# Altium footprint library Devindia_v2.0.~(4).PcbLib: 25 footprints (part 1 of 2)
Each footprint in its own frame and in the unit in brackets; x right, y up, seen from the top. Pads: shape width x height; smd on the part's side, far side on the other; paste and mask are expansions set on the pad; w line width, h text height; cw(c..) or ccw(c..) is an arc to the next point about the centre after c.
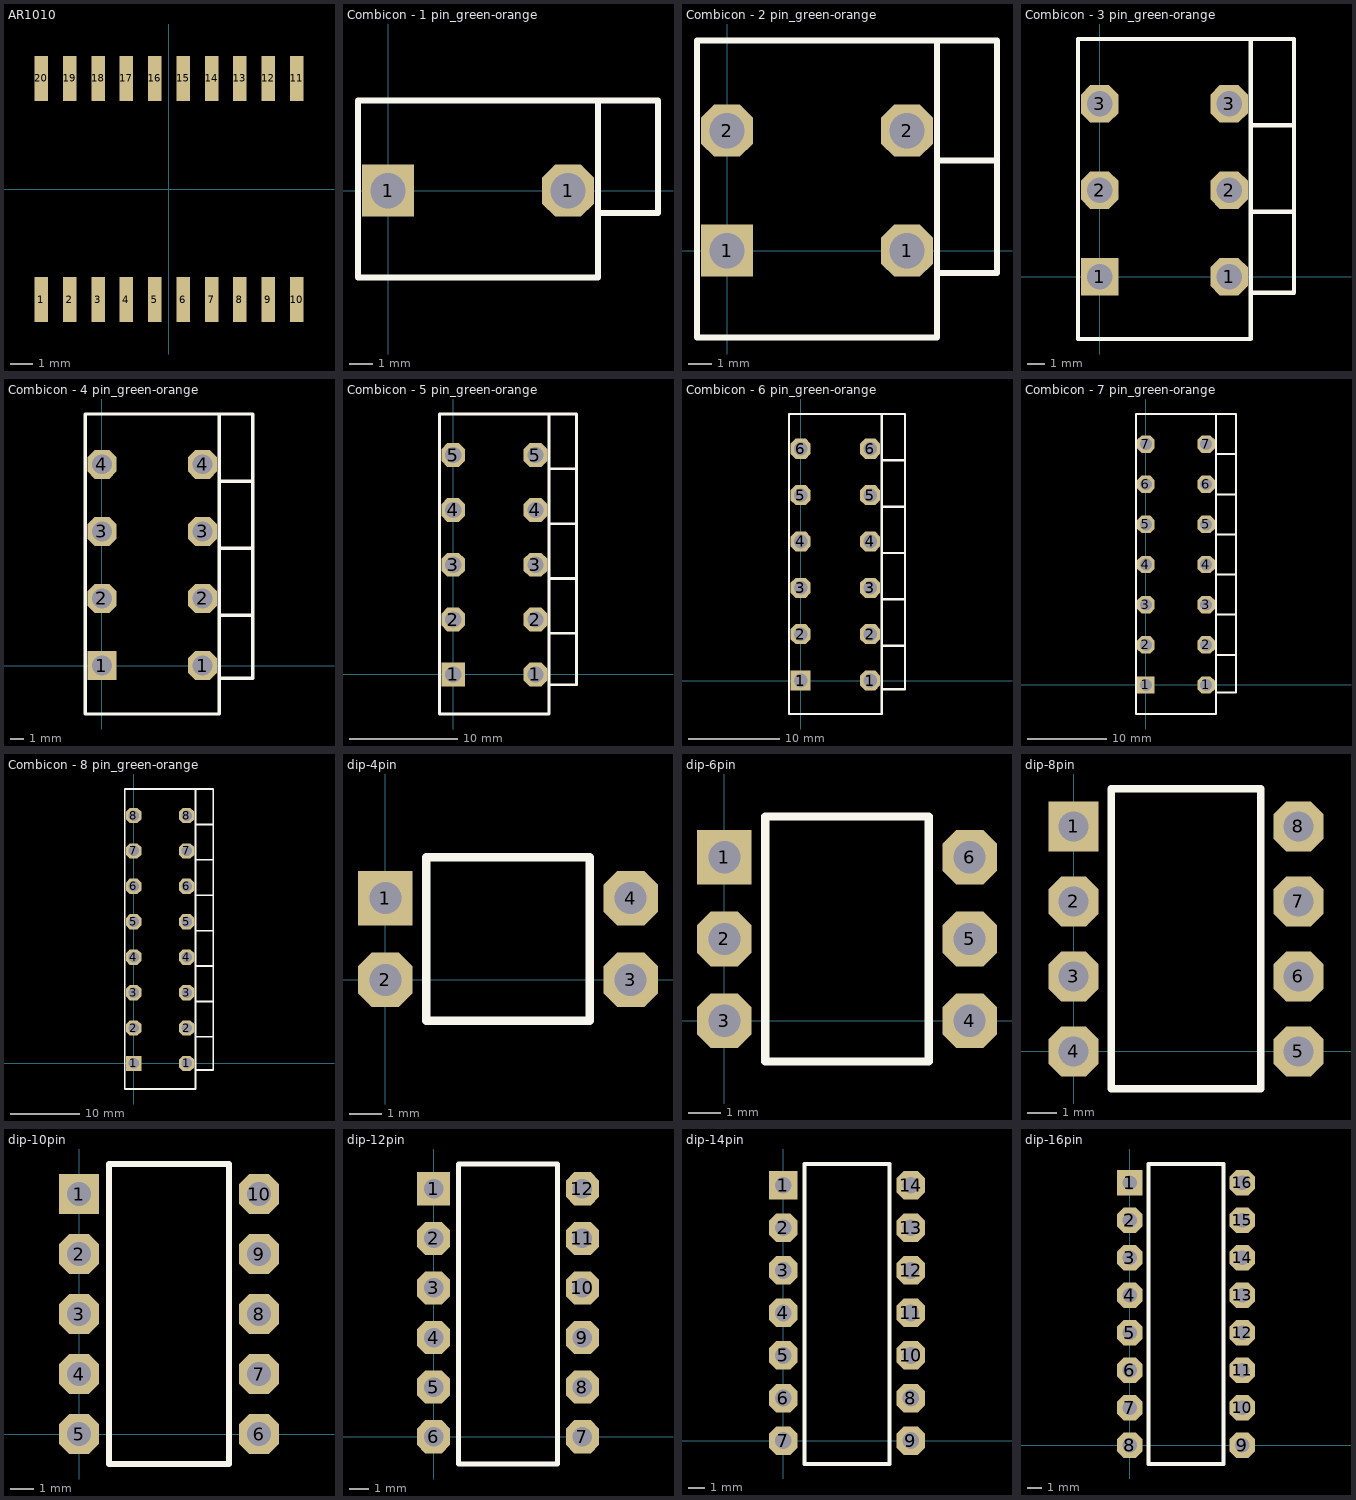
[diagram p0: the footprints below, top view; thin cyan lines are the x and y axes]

## AR1010 [mm]
pads (20):
  rect 0.6x2 smd: 1(-5.715,-4.95) 2(-4.445,-4.95) 3(-3.175,-4.95) 4(-1.905,-4.95) 5(-0.635,-4.95) 6(0.635,-4.95) 7(1.905,-4.95) 8(3.175,-4.95) 9(4.445,-4.95) 10(5.715,-4.95) 11(5.715,4.95) 12(4.445,4.95) 13(3.175,4.95) 14(1.905,4.95) 15(0.635,4.95) 16(-0.635,4.95) 17(-1.905,4.95) 18(-3.175,4.95) 19(-4.445,4.95) 20(-5.715,4.95)
Bottom Overlay:
  circle w0.254: c-5.695,-3.115 r0.284
  lines w0.254: -6.4,-3.75 -6.4,3.75 6.4,3.75 6.4,-3.75 -6.4,-3.75
3D body: height 2.15, standoff 2.05, extent -5.969,-2.54 -5.46,-2.034
3D body: height 0.32, standoff 0, extent -5.969,-5.588 -5.461,-4.318
3D body: height 1, standoff 0.16, extent -5.969,-4.445 -5.461,-4.191
3D body: height 0.32, standoff 0, extent -5.969,-4.51 -5.461,-4.191
3D body: height 1.16, standoff 0.84, extent -5.969,-4.445 -5.461,-4.126
3D body: height 1.16, standoff 0.84, extent -5.969,-4.318 -5.461,-3.175
3D body: height 0.32, standoff 0, extent -4.699,-5.588 -4.191,-4.318
3D body: height 1, standoff 0.16, extent -4.699,-4.445 -4.191,-4.191
3D body: height 0.32, standoff 0, extent -4.699,-4.51 -4.191,-4.191
3D body: height 1.16, standoff 0.84, extent -4.699,-4.445 -4.191,-4.126
3D body: height 1.16, standoff 0.84, extent -4.699,-4.318 -4.191,-3.175
3D body: height 0.32, standoff 0, extent -3.429,-5.588 -2.921,-4.318
3D body: height 1, standoff 0.16, extent -3.429,-4.445 -2.921,-4.191
3D body: height 0.32, standoff 0, extent -3.429,-4.51 -2.921,-4.191
3D body: height 1.16, standoff 0.84, extent -3.429,-4.445 -2.921,-4.126
3D body: height 1.16, standoff 0.84, extent -3.429,-4.318 -2.921,-3.175
3D body: height 0.32, standoff 0, extent -2.159,-5.588 -1.651,-4.318
3D body: height 1, standoff 0.16, extent -2.159,-4.445 -1.651,-4.191
3D body: height 0.32, standoff 0, extent -2.159,-4.51 -1.651,-4.191
3D body: height 1.16, standoff 0.84, extent -2.159,-4.445 -1.651,-4.126
3D body: height 1.16, standoff 0.84, extent -2.159,-4.318 -1.651,-3.175
3D body: height 0.32, standoff 0, extent -0.889,-5.588 -0.381,-4.318
3D body: height 1, standoff 0.16, extent -0.889,-4.445 -0.381,-4.191
3D body: height 0.32, standoff 0, extent -0.889,-4.51 -0.381,-4.191
3D body: height 1.16, standoff 0.84, extent -0.889,-4.445 -0.381,-4.126
3D body: height 1.16, standoff 0.84, extent -0.889,-4.318 -0.381,-3.175
3D body: height 0.32, standoff 0, extent 0.381,-5.588 0.889,-4.318
3D body: height 1, standoff 0.16, extent 0.381,-4.445 0.889,-4.191
3D body: height 0.32, standoff 0, extent 0.381,-4.51 0.889,-4.191
3D body: height 1.16, standoff 0.84, extent 0.381,-4.445 0.889,-4.126
3D body: height 1.16, standoff 0.84, extent 0.381,-4.318 0.889,-3.175
3D body: height 0.32, standoff 0, extent 1.651,-5.588 2.159,-4.318
3D body: height 1, standoff 0.16, extent 1.651,-4.445 2.159,-4.191
3D body: height 0.32, standoff 0, extent 1.651,-4.51 2.159,-4.191
3D body: height 1.16, standoff 0.84, extent 1.651,-4.445 2.159,-4.126
3D body: height 1.16, standoff 0.84, extent 1.651,-4.318 2.159,-3.175
3D body: height 0.32, standoff 0, extent 2.921,-5.588 3.429,-4.318
3D body: height 1, standoff 0.16, extent 2.921,-4.445 3.429,-4.191
3D body: height 0.32, standoff 0, extent 2.921,-4.51 3.429,-4.191
3D body: height 1.16, standoff 0.84, extent 2.921,-4.445 3.429,-4.126
3D body: height 1.16, standoff 0.84, extent 2.921,-4.318 3.429,-3.175
3D body: height 0.32, standoff 0, extent 4.191,-5.588 4.699,-4.318
3D body: height 1, standoff 0.16, extent 4.191,-4.445 4.699,-4.191
3D body: height 0.32, standoff 0, extent 4.191,-4.51 4.699,-4.191
3D body: height 1.16, standoff 0.84, extent 4.191,-4.445 4.699,-4.126
3D body: height 1.16, standoff 0.84, extent 4.191,-4.318 4.699,-3.175
3D body: height 0.32, standoff 0, extent 5.461,-5.588 5.969,-4.318
3D body: height 1, standoff 0.16, extent 5.461,-4.445 5.969,-4.191
3D body: height 0.32, standoff 0, extent 5.461,-4.51 5.969,-4.191
3D body: height 1.16, standoff 0.84, extent 5.461,-4.445 5.969,-4.126
3D body: height 1.16, standoff 0.84, extent 5.461,-4.318 5.969,-3.175
3D body: height 0.32, standoff 0, extent 5.461,4.318 5.969,5.588
3D body: height 1, standoff 0.16, extent 5.461,4.191 5.969,4.445
3D body: height 0.32, standoff 0, extent 5.461,4.191 5.969,4.51
3D body: height 1.16, standoff 0.84, extent 5.461,4.126 5.969,4.445
3D body: height 1.16, standoff 0.84, extent 5.461,3.175 5.969,4.318
3D body: height 0.32, standoff 0, extent 4.191,4.318 4.699,5.588
3D body: height 1, standoff 0.16, extent 4.191,4.191 4.699,4.445
3D body: height 0.32, standoff 0, extent 4.191,4.191 4.699,4.51
3D body: height 1.16, standoff 0.84, extent 4.191,4.126 4.699,4.445
3D body: height 1.16, standoff 0.84, extent 4.191,3.175 4.699,4.318
3D body: height 0.32, standoff 0, extent 2.921,4.318 3.429,5.588
3D body: height 1, standoff 0.16, extent 2.921,4.191 3.429,4.445
3D body: height 0.32, standoff 0, extent 2.921,4.191 3.429,4.51
3D body: height 1.16, standoff 0.84, extent 2.921,4.126 3.429,4.445
3D body: height 1.16, standoff 0.84, extent 2.921,3.175 3.429,4.318
3D body: height 0.32, standoff 0, extent 1.651,4.318 2.159,5.588
3D body: height 1, standoff 0.16, extent 1.651,4.191 2.159,4.445
3D body: height 0.32, standoff 0, extent 1.651,4.191 2.159,4.51
3D body: height 1.16, standoff 0.84, extent 1.651,4.126 2.159,4.445
3D body: height 1.16, standoff 0.84, extent 1.651,3.175 2.159,4.318
3D body: height 0.32, standoff 0, extent 0.381,4.318 0.889,5.588
3D body: height 1, standoff 0.16, extent 0.381,4.191 0.889,4.445
3D body: height 0.32, standoff 0, extent 0.381,4.191 0.889,4.51
3D body: height 1.16, standoff 0.84, extent 0.381,4.126 0.889,4.445
3D body: height 1.16, standoff 0.84, extent 0.381,3.175 0.889,4.318
3D body: height 0.32, standoff 0, extent -0.889,4.318 -0.381,5.588
3D body: height 1, standoff 0.16, extent -0.889,4.191 -0.381,4.445
3D body: height 0.32, standoff 0, extent -0.889,4.191 -0.381,4.51
3D body: height 1.16, standoff 0.84, extent -0.889,4.126 -0.381,4.445
3D body: height 1.16, standoff 0.84, extent -0.889,3.175 -0.381,4.318
3D body: height 0.32, standoff 0, extent -2.159,4.318 -1.651,5.588
3D body: height 1, standoff 0.16, extent -2.159,4.191 -1.651,4.445
3D body: height 0.32, standoff 0, extent -2.159,4.191 -1.651,4.51
3D body: height 1.16, standoff 0.84, extent -2.159,4.126 -1.651,4.445
3D body: height 1.16, standoff 0.84, extent -2.159,3.175 -1.651,4.318
3D body: height 0.32, standoff 0, extent -3.429,4.318 -2.921,5.588
3D body: height 1, standoff 0.16, extent -3.429,4.191 -2.921,4.445
3D body: height 0.32, standoff 0, extent -3.429,4.191 -2.921,4.51
3D body: height 1.16, standoff 0.84, extent -3.429,4.126 -2.921,4.445
3D body: height 1.16, standoff 0.84, extent -3.429,3.175 -2.921,4.318
3D body: height 0.32, standoff 0, extent -4.699,4.318 -4.191,5.588
3D body: height 1, standoff 0.16, extent -4.699,4.191 -4.191,4.445
3D body: height 1.16, standoff 0.84, extent -4.699,3.175 -4.191,4.318
3D body: height 0.32, standoff 0, extent -4.699,4.191 -4.191,4.51
3D body: height 1.16, standoff 0.84, extent -4.699,4.126 -4.191,4.445
3D body: height 0.32, standoff 0, extent -5.969,4.318 -5.461,5.588
3D body: height 1, standoff 0.16, extent -5.969,4.191 -5.461,4.445
3D body: height 1.16, standoff 0.84, extent -5.969,3.175 -5.461,4.318
3D body: height 0.32, standoff 0, extent -5.969,4.191 -5.461,4.51
3D body: height 1.16, standoff 0.84, extent -5.969,4.126 -5.461,4.445
3D body: height 1.18, standoff 0.1, extent -6.35,-3.81 6.35,3.81
3D body: height 2.05, standoff 1.05, extent -6.35,-3.175 6.35,3.175

## Combicon - 1 pin_green-orange [mm]
pads (2):
  rect 2.2x2.2 hole 1.5: 1(0,0)
  oct 2.2x2.2 hole 1.5: 1(7.62,0)
Top Overlay:
  lines w0.254: 8.956,-0.95 11.43,-0.95 11.43,3.81 8.89,3.81 ; 8.89,3.81 -1.27,3.81 -1.27,0.07 -1.27,-3.67 8.89,-3.67 8.89,3.81
3D body: height 13.66, standoff 7.75, extent 8.89,-1.016 11.43,3.81
3D body: height 13.5, standoff 13, extent 5.969,-1.503 8.864,1.397
3D body: height 13, standoff 0, extent -1.27,-3.683 8.89,3.81

## Combicon - 2 pin_green-orange [mm]
pads (4):
  rect 2.2x2.2 hole 1.5: 1(0,0)
  oct 2.2x2.2 hole 1.5: 1(7.62,0) 2(0,5.08) 2(7.62,5.08)
Top Overlay:
  lines w0.254: 8.956,-0.95 11.43,-0.95 11.43,3.81 ; 8.89,3.81 8.89,8.89 ; 8.89,3.81 8.89,-3.67 -1.27,-3.67 -1.27,0.07 -1.27,8.89 8.89,8.89 ; 8.89,3.81 11.43,3.81 ; 8.89,8.89 11.43,8.89 11.43,3.81
3D body: height 13, standoff 0, extent -1.27,-3.683 8.89,8.89
3D body: height 13.5, standoff 13, extent 5.969,-1.503 8.864,1.397
3D body: height 13.5, standoff 13, extent 5.969,3.577 8.864,6.477
3D body: height 13.66, standoff 7.75, extent 8.89,4.064 11.43,8.89
3D body: height 13.66, standoff 7.75, extent 8.89,-1.016 11.43,3.81

## Combicon - 3 pin_green-orange [mm]
pads (6):
  rect 2.2x2.2 hole 1.5: 1(0,0)
  oct 2.2x2.2 hole 1.5: 1(7.62,0) 2(0,5.08) 2(7.62,5.08) 3(0,10.16) 3(7.62,10.16)
Top Overlay:
  lines w0.254: 8.89,8.89 11.43,8.89 ; 8.956,-0.95 11.43,-0.95 11.43,3.81 ; 8.89,3.81 8.89,13.97 ; 8.89,3.81 8.89,-3.67 -1.27,-3.67 -1.27,0.07 -1.27,13.97 8.89,13.97 ; 8.89,3.81 11.43,3.81 ; 8.89,13.97 11.43,13.97 11.43,8.89 ; 11.43,3.81 11.43,8.89
3D body: height 13, standoff 0, extent -1.27,-3.683 8.89,13.97
3D body: height 13.5, standoff 13, extent 5.969,-1.503 8.864,1.397
3D body: height 13.5, standoff 13, extent 5.969,3.577 8.864,6.477
3D body: height 13.5, standoff 13, extent 5.969,8.657 8.864,11.557
3D body: height 13.66, standoff 7.75, extent 8.89,9.144 11.43,13.97
3D body: height 13.66, standoff 7.75, extent 8.89,4.064 11.43,8.89
3D body: height 13.66, standoff 7.75, extent 8.89,-1.016 11.43,3.81

## Combicon - 4 pin_green-orange [mm]
pads (8):
  rect 2.2x2.2 hole 1.5: 1(0,0)
  oct 2.2x2.2 hole 1.5: 1(7.62,0) 2(0,5.08) 2(7.62,5.08) 3(0,10.16) 3(7.62,10.16) 4(0,15.24) 4(7.62,15.24)
Top Overlay:
  lines w0.254: 8.89,8.89 11.43,8.89 ; 8.89,13.97 11.43,13.97 ; 8.956,-0.95 11.43,-0.95 11.43,3.81 ; 8.89,3.81 8.89,19.05 ; 8.89,3.81 8.89,-3.67 -1.27,-3.67 -1.27,0.07 -1.27,19.05 8.89,19.05 ; 8.89,3.81 11.43,3.81 ; 8.89,19.05 11.43,19.05 11.43,13.97 ; 11.43,3.81 11.43,8.89 ; 11.43,8.89 11.43,13.97
3D body: height 13, standoff 0, extent -1.27,-3.683 8.89,19.05
3D body: height 13.5, standoff 13, extent 5.969,-1.503 8.864,1.397
3D body: height 13.5, standoff 13, extent 5.969,3.577 8.864,6.477
3D body: height 13.5, standoff 13, extent 5.969,8.657 8.864,11.557
3D body: height 13.5, standoff 13, extent 5.969,13.737 8.864,16.637
3D body: height 13.66, standoff 7.75, extent 8.89,14.224 11.43,19.05
3D body: height 13.66, standoff 7.75, extent 8.89,9.144 11.43,13.97
3D body: height 13.66, standoff 7.75, extent 8.89,4.064 11.43,8.89
3D body: height 13.66, standoff 7.75, extent 8.89,-1.016 11.43,3.81

## Combicon - 5 pin_green-orange [mm]
pads (10):
  rect 2.2x2.2 hole 1.5: 1(0,0)
  oct 2.2x2.2 hole 1.5: 1(7.62,0) 2(0,5.08) 2(7.62,5.08) 3(0,10.16) 3(7.62,10.16) 4(0,15.24) 4(7.62,15.24) 5(0,20.32) 5(7.62,20.32)
Top Overlay:
  lines w0.254: 8.89,8.89 11.43,8.89 ; 8.89,13.97 11.43,13.97 ; 8.89,19.05 11.43,19.05 ; 8.956,-0.95 11.43,-0.95 11.43,3.81 ; 8.89,3.81 11.43,3.81 ; 8.89,3.81 8.89,-3.67 -1.27,-3.67 -1.27,0.07 -1.27,24.13 8.89,24.13 ; 8.89,3.81 8.89,24.13 ; 8.89,24.13 11.43,24.13 11.43,19.05 ; 11.43,3.81 11.43,8.89 ; 11.43,8.89 11.43,13.97 ; 11.43,13.97 11.43,19.05
3D body: height 13.66, standoff 7.75, extent 8.89,-1.016 11.43,3.81
3D body: height 13.66, standoff 7.75, extent 8.89,4.064 11.43,8.89
3D body: height 13.66, standoff 7.75, extent 8.89,9.144 11.43,13.97
3D body: height 13.66, standoff 7.75, extent 8.89,14.224 11.43,19.05
3D body: height 13.66, standoff 7.75, extent 8.89,19.304 11.43,24.13
3D body: height 13.5, standoff 13, extent 5.969,18.817 8.864,21.717
3D body: height 13.5, standoff 13, extent 5.969,13.737 8.864,16.637
3D body: height 13.5, standoff 13, extent 5.969,8.657 8.864,11.557
3D body: height 13.5, standoff 13, extent 5.969,3.577 8.864,6.477
3D body: height 13.5, standoff 13, extent 5.969,-1.503 8.864,1.397
3D body: height 13, standoff 0, extent -1.27,-3.683 8.89,24.13

## Combicon - 6 pin_green-orange [mm]
pads (12):
  rect 2.2x2.2 hole 1.5: 1(0,0)
  oct 2.2x2.2 hole 1.5: 1(7.62,0) 2(0,5.08) 2(7.62,5.08) 3(0,10.16) 3(7.62,10.16) 4(0,15.24) 4(7.62,15.24) 5(0,20.32) 5(7.62,20.32) 6(0,25.4) 6(7.62,25.4)
Top Overlay:
  lines w0.254: 8.89,8.89 11.43,8.89 ; 8.89,13.97 11.43,13.97 ; 8.89,19.05 11.43,19.05 ; 8.89,24.13 11.43,24.13 ; 8.956,-0.95 11.43,-0.95 11.43,3.81 ; 8.89,3.81 8.89,29.21 ; 8.89,3.81 8.89,-3.67 -1.27,-3.67 -1.27,0.07 -1.27,29.21 8.89,29.21 ; 8.89,3.81 11.43,3.81 ; 8.89,29.21 11.43,29.21 11.43,24.13 ; 11.43,3.81 11.43,8.89 ; 11.43,8.89 11.43,13.97 ; 11.43,13.97 11.43,19.05 ; 11.43,19.05 11.43,24.13
3D body: height 13, standoff 0, extent -1.27,-3.683 8.89,29.21
3D body: height 13.5, standoff 13, extent 5.969,-1.503 8.864,1.397
3D body: height 13.5, standoff 13, extent 5.969,3.577 8.864,6.477
3D body: height 13.5, standoff 13, extent 5.969,8.657 8.864,11.557
3D body: height 13.5, standoff 13, extent 5.969,13.737 8.864,16.637
3D body: height 13.5, standoff 13, extent 5.969,18.817 8.864,21.717
3D body: height 13.5, standoff 13, extent 5.969,23.897 8.864,26.797
3D body: height 13.66, standoff 7.75, extent 8.89,24.384 11.43,29.21
3D body: height 13.66, standoff 7.75, extent 8.89,19.304 11.43,24.13
3D body: height 13.66, standoff 7.75, extent 8.89,14.224 11.43,19.05
3D body: height 13.66, standoff 7.75, extent 8.89,9.144 11.43,13.97
3D body: height 13.66, standoff 7.75, extent 8.89,4.064 11.43,8.89
3D body: height 13.66, standoff 7.75, extent 8.89,-1.016 11.43,3.81

## Combicon - 7 pin_green-orange [mm]
pads (14):
  rect 2.2x2.2 hole 1.5: 1(0,0)
  oct 2.2x2.2 hole 1.5: 1(7.62,0) 2(0,5.08) 2(7.62,5.08) 3(0,10.16) 3(7.62,10.16) 4(0,15.24) 4(7.62,15.24) 5(0,20.32) 5(7.62,20.32) 6(0,25.4) 6(7.62,25.4) 7(0,30.48) 7(7.62,30.48)
Top Overlay:
  lines w0.254: 8.89,8.89 11.43,8.89 ; 8.89,13.97 11.43,13.97 ; 8.89,19.05 11.43,19.05 ; 8.89,24.13 11.43,24.13 ; 8.89,29.21 11.43,29.21 ; 8.956,-0.95 11.43,-0.95 11.43,3.81 ; 8.89,3.81 8.89,34.29 ; 8.89,3.81 8.89,-3.67 -1.27,-3.67 -1.27,0.07 -1.27,34.29 8.89,34.29 ; 8.89,3.81 11.43,3.81 ; 8.89,34.29 11.43,34.29 ; 8.89,34.29 11.43,34.29 ; 11.43,3.81 11.43,8.89 ; 11.43,8.89 11.43,13.97 ; 11.43,13.97 11.43,19.05 ; 11.43,19.05 11.43,24.13 ; 11.43,24.13 11.43,29.21 ; 11.43,29.21 11.43,34.29
3D body: height 13, standoff 0, extent -1.27,-3.683 8.89,34.29
3D body: height 13.5, standoff 13, extent 5.969,-1.503 8.864,1.397
3D body: height 13.5, standoff 13, extent 5.969,3.577 8.864,6.477
3D body: height 13.5, standoff 13, extent 5.969,8.657 8.864,11.557
3D body: height 13.5, standoff 13, extent 5.969,13.737 8.864,16.637
3D body: height 13.5, standoff 13, extent 5.969,18.817 8.864,21.717
3D body: height 13.5, standoff 13, extent 5.969,23.897 8.864,26.797
3D body: height 13.5, standoff 13, extent 5.969,28.977 8.864,31.877
3D body: height 13.66, standoff 7.75, extent 9.017,29.464 11.557,34.29
3D body: height 13.66, standoff 7.75, extent 8.89,24.384 11.43,29.21
3D body: height 13.66, standoff 7.75, extent 8.89,19.304 11.43,24.13
3D body: height 13.66, standoff 7.75, extent 8.89,14.224 11.43,19.05
3D body: height 13.66, standoff 7.75, extent 8.89,9.144 11.43,13.97
3D body: height 13.66, standoff 7.75, extent 8.89,4.064 11.43,8.89
3D body: height 13.66, standoff 7.75, extent 8.89,-1.016 11.43,3.81

## Combicon - 8 pin_green-orange [mm]
pads (16):
  rect 2.2x2.2 hole 1.5: 1(0,0)
  oct 2.2x2.2 hole 1.5: 1(7.62,0) 2(0,5.08) 2(7.62,5.08) 3(0,10.16) 3(7.62,10.16) 4(0,15.24) 4(7.62,15.24) 5(0,20.32) 5(7.62,20.32) 6(0,25.4) 6(7.62,25.4) 7(0,30.48) 7(7.62,30.48) 8(0,35.56) 8(7.62,35.56)
Top Overlay:
  lines w0.254: 8.89,8.89 11.43,8.89 ; 8.89,13.97 11.43,13.97 ; 8.89,19.05 11.43,19.05 ; 8.89,24.13 11.43,24.13 ; 8.89,29.21 11.43,29.21 ; 8.89,34.29 11.43,34.29 ; 8.956,-0.95 11.43,-0.95 11.43,3.81 ; 8.89,3.81 11.43,3.81 ; 8.89,3.81 8.89,-3.67 -1.27,-3.67 -1.27,0.07 -1.27,39.37 8.89,39.37 ; 8.89,3.81 8.89,39.37 ; 8.89,39.37 11.43,39.37 11.43,34.29 ; 11.43,3.81 11.43,8.89 ; 11.43,8.89 11.43,13.97 ; 11.43,13.97 11.43,19.05 ; 11.43,19.05 11.43,24.13 ; 11.43,24.13 11.43,29.21 ; 11.43,29.21 11.43,34.29
3D body: height 13.66, standoff 7.75, extent 8.89,-1.016 11.43,3.81
3D body: height 13.66, standoff 7.75, extent 8.89,4.064 11.43,8.89
3D body: height 13.66, standoff 7.75, extent 8.89,9.144 11.43,13.97
3D body: height 13.66, standoff 7.75, extent 8.89,14.224 11.43,19.05
3D body: height 13.66, standoff 7.75, extent 8.89,19.304 11.43,24.13
3D body: height 13.66, standoff 7.75, extent 8.89,24.384 11.43,29.21
3D body: height 13.66, standoff 7.75, extent 9.017,29.464 11.557,34.29
3D body: height 13.66, standoff 7.75, extent 8.89,34.544 11.43,39.37
3D body: height 13.5, standoff 13, extent 5.969,34.057 8.864,36.957
3D body: height 13.5, standoff 13, extent 5.969,28.977 8.864,31.877
3D body: height 13.5, standoff 13, extent 5.969,23.897 8.864,26.797
3D body: height 13.5, standoff 13, extent 5.969,18.817 8.864,21.717
3D body: height 13.5, standoff 13, extent 5.969,13.737 8.864,16.637
3D body: height 13.5, standoff 13, extent 5.969,8.657 8.864,11.557
3D body: height 13.5, standoff 13, extent 5.969,3.577 8.864,6.477
3D body: height 13.5, standoff 13, extent 5.969,-1.503 8.864,1.397
3D body: height 13, standoff 0, extent -1.27,-3.683 8.89,39.37

## dip-4pin [mm]
pads (4):
  rect 1.7x1.7 hole 1: 1(0,2.54)
  oct 1.7x1.7 hole 1: 2(0,0) 3(7.62,0) 4(7.62,2.54)
Top Overlay:
  lines w0.254: 1.27,-1.27 6.35,-1.27 6.35,3.81 1.27,3.81 1.27,-1.27
3D body: height 2, standoff 1.1, extent 1.27,-1.27 6.35,3.81
3D body: height 1.63, standoff 1.37, extent 0,2.159 1.905,2.921
3D body: height 1.5, standoff 0, extent -0.127,2.159 0.127,2.921
3D body: height 1.63, standoff 1.37, extent -0.126,2.159 0.126,2.921
3D body: height 1.63, standoff 1.37, extent -0.126,-0.381 0.126,0.381
3D body: height 1.5, standoff 0, extent -0.127,-0.381 0.127,0.381
3D body: height 1.63, standoff 1.37, extent 0,-0.381 1.905,0.381
3D body: height 1.63, standoff 1.37, extent 7.494,-0.381 7.746,0.381
3D body: height 1.5, standoff 0, extent 7.493,-0.381 7.747,0.381
3D body: height 1.63, standoff 1.37, extent 5.715,-0.381 7.62,0.381
3D body: height 1.63, standoff 1.37, extent 7.494,2.159 7.746,2.921
3D body: height 1.5, standoff 0, extent 7.493,2.159 7.747,2.921
3D body: height 1.63, standoff 1.37, extent 5.715,2.159 7.62,2.921
3D body: height 2.51, standoff 2.5, extent 2.286,2.032 3.284,3.028
3D body: height 2.5, standoff 2, extent 1.778,-1.27 5.842,3.81

## dip-6pin [mm]
pads (6):
  rect 1.7x1.7 hole 1: 1(0,5.08)
  oct 1.7x1.7 hole 1: 2(0,2.54) 3(0,0) 4(7.62,0) 5(7.62,2.54) 6(7.62,5.08)
Top Overlay:
  lines w0.254: 1.27,-1.27 6.35,-1.27 6.35,6.35 1.27,6.35 1.27,-1.27
3D body: height 1.63, standoff 1.37, extent -0.127,2.159 1.778,2.921
3D body: height 1.63, standoff 1.37, extent -0.127,4.699 1.778,5.461
3D body: height 1.63, standoff 1.37, extent -0.127,-0.381 1.778,0.381
3D body: height 1.63, standoff 1.37, extent 5.842,-0.381 7.747,0.381
3D body: height 1.63, standoff 1.37, extent 5.842,2.159 7.747,2.921
3D body: height 1.63, standoff 1.37, extent 5.842,4.699 7.747,5.461
3D body: height 1.63, standoff 1.37, extent -0.126,4.699 0.126,5.461
3D body: height 1.5, standoff 0, extent -0.127,4.699 0.127,5.461
3D body: height 1.63, standoff 1.37, extent -0.126,2.159 0.126,2.921
3D body: height 1.5, standoff 0, extent -0.127,2.159 0.127,2.921
3D body: height 1.63, standoff 1.37, extent -0.126,-0.381 0.126,0.381
3D body: height 1.5, standoff 0, extent -0.127,-0.381 0.127,0.381
3D body: height 1.63, standoff 1.37, extent 7.494,-0.381 7.746,0.381
3D body: height 1.5, standoff 0, extent 7.493,-0.381 7.747,0.381
3D body: height 1.63, standoff 1.37, extent 7.494,2.159 7.746,2.921
3D body: height 1.5, standoff 0, extent 7.493,2.159 7.747,2.921
3D body: height 1.63, standoff 1.37, extent 7.494,4.699 7.746,5.461
3D body: height 1.5, standoff 0, extent 7.493,4.699 7.747,5.461
3D body: height 2, standoff 1.1, extent 1.27,-1.27 6.35,6.35
3D body: height 2.51, standoff 2.5, extent 2.041,4.592 3.039,5.588
3D body: height 2.5, standoff 2, extent 1.778,-1.27 5.842,6.35

## dip-8pin [mm]
pads (8):
  rect 1.7x1.7 hole 1: 1(0,7.62)
  oct 1.7x1.7 hole 1: 2(0,5.08) 3(0,2.54) 4(0,0) 5(7.62,0) 6(7.62,2.54) 7(7.62,5.08) 8(7.62,7.62)
Top Overlay:
  lines w0.254: 1.27,-1.27 6.35,-1.27 6.35,8.89 1.27,8.89 1.27,-1.27
3D body: height 1.63, standoff 1.37, extent -0.127,4.699 1.778,5.461
3D body: height 1.63, standoff 1.37, extent -0.127,7.239 1.778,8.001
3D body: height 1.63, standoff 1.37, extent -0.127,2.159 1.778,2.921
3D body: height 1.63, standoff 1.37, extent -0.127,-0.381 1.778,0.381
3D body: height 1.63, standoff 1.37, extent 5.842,-0.381 7.747,0.381
3D body: height 1.63, standoff 1.37, extent 5.842,2.159 7.747,2.921
3D body: height 1.63, standoff 1.37, extent 5.842,4.699 7.747,5.461
3D body: height 1.63, standoff 1.37, extent 5.842,7.239 7.747,8.001
3D body: height 1.63, standoff 1.37, extent -0.126,7.239 0.126,8.001
3D body: height 1.5, standoff 0, extent -0.127,7.239 0.127,8.001
3D body: height 1.63, standoff 1.37, extent -0.126,4.699 0.126,5.461
3D body: height 1.5, standoff 0, extent -0.127,4.699 0.127,5.461
3D body: height 1.63, standoff 1.37, extent -0.126,2.159 0.126,2.921
3D body: height 1.5, standoff 0, extent -0.127,2.159 0.127,2.921
3D body: height 1.63, standoff 1.37, extent -0.126,-0.381 0.126,0.381
3D body: height 1.5, standoff 0, extent -0.127,-0.381 0.127,0.381
3D body: height 1.63, standoff 1.37, extent 7.494,-0.381 7.746,0.381
3D body: height 1.5, standoff 0, extent 7.493,-0.381 7.747,0.381
3D body: height 1.63, standoff 1.37, extent 7.494,2.159 7.746,2.921
3D body: height 1.5, standoff 0, extent 7.493,2.159 7.747,2.921
3D body: height 1.63, standoff 1.37, extent 7.494,4.699 7.746,5.461
3D body: height 1.5, standoff 0, extent 7.493,4.699 7.747,5.461
3D body: height 1.63, standoff 1.37, extent 7.494,7.239 7.746,8.001
3D body: height 1.5, standoff 0, extent 7.493,7.239 7.747,8.001
3D body: height 2, standoff 1.1, extent 1.27,-1.27 6.35,8.89
3D body: height 2.51, standoff 2.5, extent 2.041,7.132 3.039,8.128
3D body: height 2.5, standoff 2, extent 1.778,-1.27 5.842,8.89

## dip-10pin [mm]
pads (10):
  rect 1.7x1.7 hole 1: 1(0,10.16)
  oct 1.7x1.7 hole 1: 2(0,7.62) 3(0,5.08) 4(0,2.54) 5(0,0) 6(7.62,0) 7(7.62,2.54) 8(7.62,5.08) 9(7.62,7.62) 10(7.62,10.16)
Top Overlay:
  lines w0.254: 1.27,-1.27 6.35,-1.27 6.35,11.43 1.27,11.43 1.27,-1.27
3D body: height 1.5, standoff 0, extent 7.493,4.699 7.747,5.461
3D body: height 1.63, standoff 1.37, extent 7.494,4.699 7.746,5.461
3D body: height 1.63, standoff 1.37, extent 5.842,4.699 7.747,5.461
3D body: height 1.63, standoff 1.37, extent -0.127,7.239 1.778,8.001
3D body: height 1.63, standoff 1.37, extent -0.127,9.779 1.778,10.541
3D body: height 1.63, standoff 1.37, extent -0.127,4.699 1.778,5.461
3D body: height 1.63, standoff 1.37, extent -0.127,2.159 1.778,2.921
3D body: height 1.63, standoff 1.37, extent -0.127,-0.381 1.778,0.381
3D body: height 1.63, standoff 1.37, extent 5.842,-0.381 7.747,0.381
3D body: height 1.63, standoff 1.37, extent 5.842,2.159 7.747,2.921
3D body: height 1.63, standoff 1.37, extent 5.842,9.779 7.747,10.541
3D body: height 1.63, standoff 1.37, extent -0.126,9.779 0.126,10.541
3D body: height 1.5, standoff 0, extent -0.127,9.779 0.127,10.541
3D body: height 1.63, standoff 1.37, extent -0.126,7.239 0.126,8.001
3D body: height 1.5, standoff 0, extent -0.127,7.239 0.127,8.001
3D body: height 1.63, standoff 1.37, extent -0.126,4.699 0.126,5.461
3D body: height 1.5, standoff 0, extent -0.127,4.699 0.127,5.461
3D body: height 1.63, standoff 1.37, extent -0.126,2.159 0.126,2.921
3D body: height 1.5, standoff 0, extent -0.127,2.159 0.127,2.921
3D body: height 1.63, standoff 1.37, extent -0.126,-0.381 0.126,0.381
3D body: height 1.5, standoff 0, extent -0.127,-0.381 0.127,0.381
3D body: height 1.63, standoff 1.37, extent 7.494,-0.381 7.746,0.381
3D body: height 1.5, standoff 0, extent 7.493,-0.381 7.747,0.381
3D body: height 1.63, standoff 1.37, extent 7.494,2.159 7.746,2.921
3D body: height 1.5, standoff 0, extent 7.493,2.159 7.747,2.921
3D body: height 1.63, standoff 1.37, extent 7.494,9.779 7.746,10.541
3D body: height 1.5, standoff 0, extent 7.493,9.779 7.747,10.541
3D body: height 2, standoff 1.1, extent 1.27,-1.27 6.35,11.43
3D body: height 2.51, standoff 2.5, extent 2.041,9.672 3.039,10.668
3D body: height 2.5, standoff 2, extent 1.778,-1.27 5.842,11.43
3D body: height 1.63, standoff 1.37, extent 5.842,7.239 7.747,8.001
3D body: height 1.63, standoff 1.37, extent 7.494,7.239 7.746,8.001
3D body: height 1.5, standoff 0, extent 7.493,7.239 7.747,8.001

## dip-12pin [mm]
pads (12):
  rect 1.7x1.7 hole 1: 1(0,12.7)
  oct 1.7x1.7 hole 1: 2(0,10.16) 3(0,7.62) 4(0,5.08) 5(0,2.54) 6(0,0) 7(7.62,0) 8(7.62,2.54) 9(7.62,5.08) 10(7.62,7.62) 11(7.62,10.16) 12(7.62,12.7)
Top Overlay:
  lines w0.254: 1.27,-1.397 1.27,13.97 6.35,13.97 6.35,-1.397 1.27,-1.397
3D body: height 1.5, standoff 0, extent 7.493,4.699 7.747,5.461
3D body: height 1.63, standoff 1.37, extent 7.494,4.699 7.746,5.461
3D body: height 1.63, standoff 1.37, extent 5.842,4.699 7.747,5.461
3D body: height 2.5, standoff 2, extent 1.778,-1.27 5.842,13.97
3D body: height 2.51, standoff 2.5, extent 2.041,12.212 3.039,13.208
3D body: height 2, standoff 1.1, extent 1.27,-1.397 6.35,13.97
3D body: height 1.5, standoff 0, extent 7.493,12.319 7.747,13.081
3D body: height 1.63, standoff 1.37, extent 7.494,12.319 7.746,13.081
3D body: height 1.5, standoff 0, extent 7.493,9.779 7.747,10.541
3D body: height 1.63, standoff 1.37, extent 7.494,9.779 7.746,10.541
3D body: height 1.5, standoff 0, extent 7.493,7.239 7.747,8.001
3D body: height 1.63, standoff 1.37, extent 7.494,7.239 7.746,8.001
3D body: height 1.5, standoff 0, extent 7.493,2.159 7.747,2.921
3D body: height 1.63, standoff 1.37, extent 7.494,2.159 7.746,2.921
3D body: height 1.5, standoff 0, extent 7.493,-0.381 7.747,0.381
3D body: height 1.63, standoff 1.37, extent 7.494,-0.381 7.746,0.381
3D body: height 1.5, standoff 0, extent -0.127,-0.381 0.127,0.381
3D body: height 1.63, standoff 1.37, extent -0.126,-0.381 0.126,0.381
3D body: height 1.5, standoff 0, extent -0.127,2.159 0.127,2.921
3D body: height 1.63, standoff 1.37, extent -0.126,2.159 0.126,2.921
3D body: height 1.5, standoff 0, extent -0.127,4.699 0.127,5.461
3D body: height 1.63, standoff 1.37, extent -0.126,4.699 0.126,5.461
3D body: height 1.5, standoff 0, extent -0.127,7.239 0.127,8.001
3D body: height 1.63, standoff 1.37, extent -0.126,7.239 0.126,8.001
3D body: height 1.5, standoff 0, extent -0.127,9.779 0.127,10.541
3D body: height 1.63, standoff 1.37, extent -0.126,9.779 0.126,10.541
3D body: height 1.5, standoff 0, extent -0.127,12.319 0.127,13.081
3D body: height 1.63, standoff 1.37, extent -0.126,12.319 0.126,13.081
3D body: height 1.63, standoff 1.37, extent 5.842,12.319 7.747,13.081
3D body: height 1.63, standoff 1.37, extent 5.842,9.779 7.747,10.541
3D body: height 1.63, standoff 1.37, extent 5.842,7.239 7.747,8.001
3D body: height 1.63, standoff 1.37, extent 5.842,2.159 7.747,2.921
3D body: height 1.63, standoff 1.37, extent 5.842,-0.381 7.747,0.381
3D body: height 1.63, standoff 1.37, extent -0.127,-0.381 1.778,0.381
3D body: height 1.63, standoff 1.37, extent -0.127,2.159 1.778,2.921
3D body: height 1.63, standoff 1.37, extent -0.127,4.699 1.778,5.461
3D body: height 1.63, standoff 1.37, extent -0.127,7.239 1.778,8.001
3D body: height 1.63, standoff 1.37, extent -0.127,12.319 1.778,13.081
3D body: height 1.63, standoff 1.37, extent -0.127,9.779 1.778,10.541

## dip-14pin [mm]
pads (14):
  rect 1.7x1.7 hole 1: 1(0,15.24)
  oct 1.7x1.7 hole 1: 2(0,12.7) 3(0,10.16) 4(0,7.62) 5(0,5.08) 6(0,2.54) 7(0,0) 8(7.62,2.54) 9(7.62,0) 10(7.62,5.08) 11(7.62,7.62) 12(7.62,10.16) 13(7.62,12.7) 14(7.62,15.24)
Top Overlay:
  lines w0.254: 1.27,-1.397 6.35,-1.397 6.35,16.51 1.27,16.51 1.27,-1.397
3D body: height 1.5, standoff 0, extent 7.493,2.159 7.747,2.921
3D body: height 1.63, standoff 1.37, extent 7.494,2.159 7.746,2.921
3D body: height 1.63, standoff 1.37, extent 5.842,2.159 7.747,2.921
3D body: height 1.63, standoff 1.37, extent 7.621,14.859 7.873,15.621
3D body: height 1.5, standoff 0, extent 7.62,14.859 7.874,15.621
3D body: height 1.63, standoff 1.37, extent 5.842,14.859 7.747,15.621
3D body: height 1.63, standoff 1.37, extent 5.842,12.319 7.747,13.081
3D body: height 1.5, standoff 0, extent 7.62,12.319 7.874,13.081
3D body: height 1.63, standoff 1.37, extent 7.621,12.319 7.873,13.081
3D body: height 1.63, standoff 1.37, extent -0.127,12.319 1.778,13.081
3D body: height 1.63, standoff 1.37, extent -0.127,14.859 1.778,15.621
3D body: height 1.63, standoff 1.37, extent -0.127,9.779 1.778,10.541
3D body: height 1.63, standoff 1.37, extent -0.127,7.239 1.778,8.001
3D body: height 1.63, standoff 1.37, extent -0.127,4.699 1.778,5.461
3D body: height 1.63, standoff 1.37, extent -0.127,2.159 1.778,2.921
3D body: height 1.63, standoff 1.37, extent -0.127,-0.381 1.778,0.381
3D body: height 1.63, standoff 1.37, extent 5.842,-0.381 7.747,0.381
3D body: height 1.63, standoff 1.37, extent 5.842,4.699 7.747,5.461
3D body: height 1.63, standoff 1.37, extent 5.842,7.239 7.747,8.001
3D body: height 1.63, standoff 1.37, extent 5.842,9.779 7.747,10.541
3D body: height 1.63, standoff 1.37, extent -0.126,14.859 0.126,15.621
3D body: height 1.5, standoff 0, extent -0.127,14.859 0.127,15.621
3D body: height 1.63, standoff 1.37, extent -0.126,12.319 0.126,13.081
3D body: height 1.5, standoff 0, extent -0.127,12.319 0.127,13.081
3D body: height 1.63, standoff 1.37, extent -0.126,9.779 0.126,10.541
3D body: height 1.5, standoff 0, extent -0.127,9.779 0.127,10.541
3D body: height 1.63, standoff 1.37, extent -0.126,7.239 0.126,8.001
3D body: height 1.5, standoff 0, extent -0.127,7.239 0.127,8.001
3D body: height 1.63, standoff 1.37, extent -0.126,4.699 0.126,5.461
3D body: height 1.5, standoff 0, extent -0.127,4.699 0.127,5.461
3D body: height 1.63, standoff 1.37, extent -0.126,2.159 0.126,2.921
3D body: height 1.5, standoff 0, extent -0.127,2.159 0.127,2.921
3D body: height 1.63, standoff 1.37, extent -0.126,-0.381 0.126,0.381
3D body: height 1.5, standoff 0, extent -0.127,-0.381 0.127,0.381
3D body: height 1.63, standoff 1.37, extent 7.494,-0.381 7.746,0.381
3D body: height 1.5, standoff 0, extent 7.493,-0.381 7.747,0.381
3D body: height 1.63, standoff 1.37, extent 7.494,4.699 7.746,5.461
3D body: height 1.5, standoff 0, extent 7.493,4.699 7.747,5.461
3D body: height 1.63, standoff 1.37, extent 7.494,7.239 7.746,8.001
3D body: height 1.5, standoff 0, extent 7.493,7.239 7.747,8.001
3D body: height 1.63, standoff 1.37, extent 7.494,9.779 7.746,10.541
3D body: height 1.5, standoff 0, extent 7.493,9.779 7.747,10.541
3D body: height 2, standoff 1.1, extent 1.27,-1.27 6.35,16.51
3D body: height 2.51, standoff 2.5, extent 2.041,14.752 3.039,15.748
3D body: height 2.5, standoff 2, extent 1.778,-1.397 5.842,16.51

## dip-16pin [mm]
pads (16):
  rect 1.7x1.7 hole 1: 1(0,17.78)
  oct 1.7x1.7 hole 1: 2(0,15.24) 3(0,12.7) 4(0,10.16) 5(0,7.62) 6(0,5.08) 7(0,2.54) 8(0,0) 9(7.62,0) 10(7.62,2.54) 11(7.62,5.08) 12(7.62,7.62) 13(7.62,10.16) 14(7.62,12.7) 15(7.62,15.24) 16(7.62,17.78)
Top Overlay:
  lines w0.254: 1.27,-1.27 1.27,19.05 6.35,19.05 6.35,-1.27 1.27,-1.27
3D body: height 1.63, standoff 1.37, extent 7.621,12.319 7.873,13.081
3D body: height 1.5, standoff 0, extent 7.62,12.319 7.874,13.081
3D body: height 1.63, standoff 1.37, extent 5.842,12.319 7.747,13.081
3D body: height 2.5, standoff 2, extent 1.778,-1.27 5.842,19.05
3D body: height 2.51, standoff 2.5, extent 2.041,17.292 3.039,18.288
3D body: height 1.5, standoff 0, extent 7.493,17.399 7.747,18.161
3D body: height 1.63, standoff 1.37, extent 7.494,17.399 7.746,18.161
3D body: height 2, standoff 1.1, extent 1.27,-1.27 6.35,19.05
3D body: height 1.5, standoff 0, extent 7.493,7.239 7.747,8.001
3D body: height 1.63, standoff 1.37, extent 7.494,7.239 7.746,8.001
3D body: height 1.5, standoff 0, extent 7.493,4.699 7.747,5.461
3D body: height 1.63, standoff 1.37, extent 7.494,4.699 7.746,5.461
3D body: height 1.5, standoff 0, extent 7.493,2.159 7.747,2.921
3D body: height 1.63, standoff 1.37, extent 7.494,2.159 7.746,2.921
3D body: height 1.5, standoff 0, extent 7.493,-0.381 7.747,0.381
3D body: height 1.63, standoff 1.37, extent 7.494,-0.381 7.746,0.381
3D body: height 1.5, standoff 0, extent -0.127,-0.381 0.127,0.381
3D body: height 1.63, standoff 1.37, extent -0.126,-0.381 0.126,0.381
3D body: height 1.5, standoff 0, extent -0.127,2.159 0.127,2.921
3D body: height 1.63, standoff 1.37, extent -0.126,2.159 0.126,2.921
3D body: height 1.5, standoff 0, extent -0.127,4.699 0.127,5.461
3D body: height 1.63, standoff 1.37, extent -0.126,4.699 0.126,5.461
3D body: height 1.5, standoff 0, extent -0.127,7.239 0.127,8.001
3D body: height 1.63, standoff 1.37, extent -0.126,7.239 0.126,8.001
3D body: height 1.5, standoff 0, extent -0.127,9.779 0.127,10.541
3D body: height 1.63, standoff 1.37, extent -0.126,9.779 0.126,10.541
3D body: height 1.5, standoff 0, extent -0.127,12.319 0.127,13.081
3D body: height 1.63, standoff 1.37, extent -0.126,12.319 0.126,13.081
3D body: height 1.5, standoff 0, extent -0.127,14.859 0.127,15.621
3D body: height 1.63, standoff 1.37, extent -0.126,14.859 0.126,15.621
3D body: height 1.5, standoff 0, extent -0.127,17.399 0.127,18.161
3D body: height 1.63, standoff 1.37, extent -0.126,17.399 0.126,18.161
3D body: height 1.63, standoff 1.37, extent 5.842,7.239 7.747,8.001
3D body: height 1.63, standoff 1.37, extent 5.842,4.699 7.747,5.461
3D body: height 1.63, standoff 1.37, extent 5.842,2.159 7.747,2.921
3D body: height 1.63, standoff 1.37, extent 5.842,-0.381 7.747,0.381
3D body: height 1.63, standoff 1.37, extent -0.127,-0.381 1.778,0.381
3D body: height 1.63, standoff 1.37, extent -0.127,2.159 1.778,2.921
3D body: height 1.63, standoff 1.37, extent -0.127,4.699 1.778,5.461
3D body: height 1.63, standoff 1.37, extent -0.127,7.239 1.778,8.001
3D body: height 1.63, standoff 1.37, extent -0.127,9.779 1.778,10.541
3D body: height 1.63, standoff 1.37, extent -0.127,12.319 1.778,13.081
3D body: height 1.63, standoff 1.37, extent -0.127,17.399 1.778,18.161
3D body: height 1.63, standoff 1.37, extent -0.127,14.859 1.778,15.621
3D body: height 1.63, standoff 1.37, extent 7.621,9.779 7.873,10.541
3D body: height 1.5, standoff 0, extent 7.62,9.779 7.874,10.541
3D body: height 1.63, standoff 1.37, extent 5.842,9.779 7.747,10.541
3D body: height 1.63, standoff 1.37, extent 5.842,14.859 7.747,15.621
3D body: height 1.63, standoff 1.37, extent 5.842,17.399 7.747,18.161
3D body: height 1.5, standoff 0, extent 7.62,17.399 7.874,18.161
3D body: height 1.63, standoff 1.37, extent 7.621,17.399 7.873,18.161
3D body: height 1.5, standoff 0, extent 7.62,14.859 7.874,15.621
3D body: height 1.63, standoff 1.37, extent 7.621,14.859 7.873,15.621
